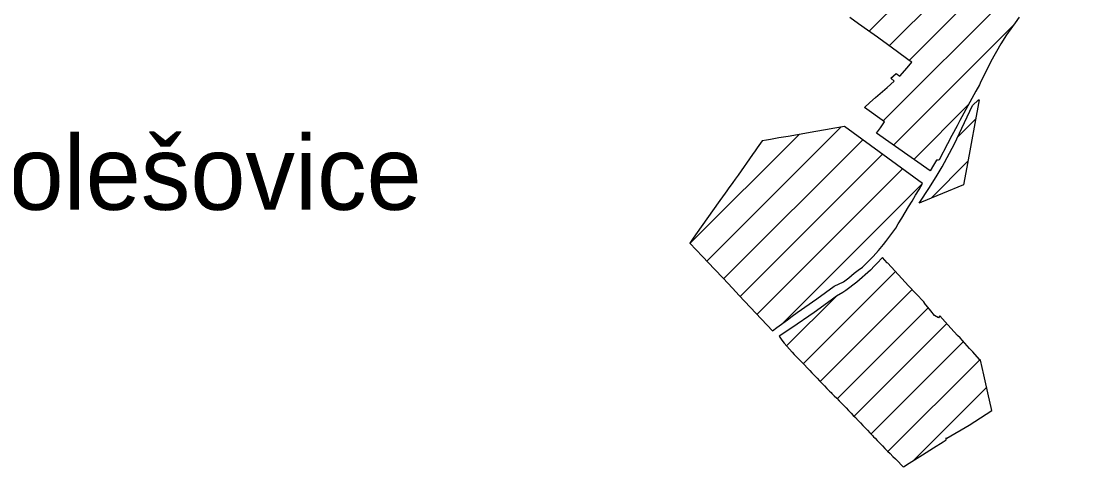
# Model space of a CAD drawing. Extents: x -552716 to -540720, y -1192685 to -1177912.
# Drawn here: x -547709 to -545764, y -1186023 to -1185200 of the extents above; entities that cross this region are included whole.
import ezdxf

# ---------------------------------------------------------------- set-up
doc = ezdxf.new("R2010")
doc.units = 0
for name, color, linetype in [('Default', 7, 'Continuous'), ('Vrstva 1', 7, 'Continuous'), ('Vrstva 2', 7, 'Continuous')]:
    doc.layers.add(name, color=color, linetype=linetype)

msp = doc.modelspace()

# ---------------------------------------------------------------- linework, layer by layer
at = {"layer": 'Default'}
for points in [[(-546032.8, -1185476.8), (-546131.5, -1185407.2), (-546124.2, -1185397.1), (-546116.6, -1185386.4), (-546153.9, -1185359.5), (-546143.8, -1185350.6), (-546133.2, -1185341.3), (-546112.1, -1185322.6), (-546098.8, -1185310.9), (-546105.4, -1185305.9), (-546095.4, -1185296.8), (-546088.6, -1185301.8), (-546075.2, -1185286.3), (-546066.4, -1185276.4), (-546072.9, -1185271.6), (-546073.8, -1185271), (-546093, -1185256.9), (-546111.2, -1185243.6), (-546127, -1185232.1), (-546129.5, -1185230.3), (-546148.3, -1185216.9), (-546164.6, -1185205.2), (-546181, -1185193.5)], [(-545868.2, -1185193.3), (-545875.9, -1185203.4), (-545891.6, -1185225.4), (-545902, -1185242.2), (-545921, -1185275.1), (-545933.9, -1185301.3), (-545939, -1185311.9), (-545941.9, -1185317.7), (-545948.1, -1185329.7), (-545977.7, -1185383.6), (-545981.8, -1185391), (-545983.1, -1185393.3), (-545992.6, -1185411.5), (-546000.8, -1185427.1), (-546016.1, -1185456.1), (-546018.1, -1185456.7), (-546019.9, -1185456.8), (-546020.9, -1185456.8), (-546026.4, -1185466.2), (-546032.8, -1185476.8)], [(-546190.8, -1185394.7), (-546208.3, -1185397.7), (-546225.8, -1185400.8), (-546243.2, -1185403.9), (-546260.4, -1185406.9), (-546277.6, -1185409.9), (-546294.7, -1185413), (-546311.9, -1185416), (-546327.1, -1185418.7), (-546334.7, -1185420), (-546342.3, -1185421.4), (-546351.5, -1185434.3), (-546355.5, -1185439.9), (-546360.3, -1185446.7), (-546387, -1185484.4), (-546392.4, -1185491.9), (-546396.8, -1185498.2), (-546401.4, -1185504.6), (-546403.9, -1185508.2), (-546407.5, -1185513.3), (-546410.7, -1185517.7), (-546420.4, -1185531.5), (-546465.2, -1185594.6), (-546470.7, -1185602.4), (-546476.1, -1185609.9), (-546452.7, -1185634.5), (-546430.6, -1185657.9), (-546414.7, -1185674.7), (-546397.5, -1185693), (-546384.8, -1185706.7), (-546323.2, -1185771.6), (-546315.4, -1185765.8), (-546295.7, -1185751.2), (-546287.2, -1185744.9), (-546278.1, -1185738.1), (-546241.9, -1185712.8), (-546209.4, -1185689.4), (-546192.4, -1185681.7), (-546182.9, -1185673.9), (-546172.8, -1185665.7), (-546165.2, -1185660), (-546157.4, -1185654.2), (-546147.1, -1185644.1), (-546137.9, -1185634.5), (-546127.7, -1185623.7), (-546118.4, -1185612.3), (-546114.3, -1185606.8), (-546110.8, -1185602.1), (-546096.1, -1185582.5), (-546091.4, -1185574.7), (-546085.1, -1185564.2), (-546078.8, -1185553.6), (-546072.4, -1185543), (-546066.1, -1185532.4), (-546059.6, -1185521.6), (-546053.1, -1185510.8), (-546046.6, -1185499.9), (-546190.8, -1185394.7)], [(-546311.4, -1185781.9), (-546306, -1185789.2), (-546302, -1185794.3), (-546297.2, -1185800.1), (-546292.3, -1185805.7), (-546287.4, -1185811), (-546283.2, -1185815.4), (-546278.7, -1185820.1), (-546273.6, -1185825.4), (-546269.3, -1185829.9), (-546264.6, -1185834.8), (-546259.5, -1185840.1), (-546254.8, -1185844.9), (-546250.6, -1185849.3), (-546245.7, -1185854.4), (-546241.1, -1185859.1), (-546236.5, -1185863.9), (-546232.3, -1185868.3), (-546227.5, -1185873.2), (-546222.9, -1185878.1), (-546218.2, -1185882.9), (-546215.5, -1185885.7), (-546214.1, -1185887.2), (-546209.4, -1185891.8), (-546205, -1185896.3), (-546200.6, -1185900.7), (-546196.1, -1185905.2), (-546191.6, -1185909.7), (-546187.7, -1185913.8), (-546183, -1185918.7), (-546178.5, -1185923.4), (-546174.4, -1185927.7), (-546170.5, -1185931.8), (-546165.3, -1185937.2), (-546161, -1185941.8), (-546156.5, -1185946.5), (-546151.4, -1185951.9), (-546148.1, -1185955.3), (-546143.7, -1185960), (-546139.2, -1185964.7), (-546136.9, -1185967.2), (-546134.3, -1185969.9), (-546130.3, -1185974.1), (-546125.4, -1185979.2), (-546120.6, -1185984.1), (-546116.1, -1185988.9), (-546111, -1185994), (-546106.5, -1185998.4), (-546101.3, -1186003.7), (-546096.7, -1186008.2), (-546091.3, -1186013.7), (-546086.2, -1186018.8), (-546083.2, -1186021.8), (-546082.2, -1186022.9), (-546080.6, -1186021.8), (-546076.5, -1186019.2), (-546047, -1186000.5), (-546026.6, -1185987.7), (-546008.9, -1185976.4), (-546003, -1185972.6), (-546002.8, -1185969.5), (-546001.7, -1185969.6), (-545960.7, -1185945.6), (-545918.7, -1185918.8), (-545926, -1185885.9), (-545933.7, -1185852.9), (-545939.8, -1185826.2), (-545941.4, -1185824.5), (-545954.2, -1185810.5), (-545959.8, -1185804.3), (-545977.5, -1185784.9), (-545981.9, -1185780.2), (-545994.2, -1185766.6), (-546010, -1185749.4), (-546014.8, -1185744.2), (-546017.4, -1185747.8), (-546024.7, -1185743.3), (-546031.5, -1185735), (-546043.2, -1185720.5), (-546043, -1185720.1), (-546044.3, -1185718.6), (-546058.4, -1185703.3), (-546072.3, -1185688.9), (-546085, -1185675.1), (-546097.7, -1185661.2), (-546110.9, -1185647.1), (-546111.7, -1185646.2), (-546120.7, -1185636.6), (-546130.9, -1185647.6), (-546135.1, -1185652), (-546142.9, -1185659.6), (-546167.8, -1185681.8), (-546188.3, -1185697.2), (-546193.9, -1185700.9), (-546205.6, -1185708.1), (-546215.5, -1185715.4), (-546246.6, -1185737.9), (-546287.6, -1185766.5), (-546311.4, -1185781.9)]]:
    msp.add_lwpolyline(points, dxfattribs=at)
msp.add_lwpolyline([(-545971, -1185502.5), (-546048.8, -1185534.4), (-546052.7, -1185536), (-546034.1, -1185507.4), (-546019.5, -1185484.8), (-546010.2, -1185469.5), (-545987.9, -1185426.8), (-545983.6, -1185417.7), (-545969.1, -1185387.4), (-545954.3, -1185356.2), (-545943.6, -1185345.5), (-545942.4, -1185345.6), (-545964.8, -1185469.6)], close=True, dxfattribs=at)
at = {"layer": 'Vrstva 2'}
for p, q in [((-546145, -1185219.2), (-545826.9, -1184901.1)), ((-546108, -1185245.9), (-545806.3, -1184944.2)), ((-546071.3, -1185272.8), (-545797.4, -1184998.9)), ((-546119.3, -1185384.5), (-545763.8, -1185029)), ((-546100.4, -1185429.2), (-545879.2, -1185208)), ((-546104.8, -1185306.3), (-546095.3, -1185296.8)), ((-546063, -1185455.5), (-545961.3, -1185353.8)), ((-546444.6, -1185643.1), (-546197.3, -1185395.8)), ((-545982, -1185414.5), (-545948.8, -1185381.3)), ((-546475.6, -1185610.5), (-546274.5, -1185409.4)), ((-546413.6, -1185675.8), (-546157.1, -1185419.3)), ((-546382.9, -1185708.7), (-546120.3, -1185446.1)), ((-546351.9, -1185741.3), (-546083.5, -1185473)), ((-546031, -1185527.1), (-545962.9, -1185459)), ((-546305.1, -1185758.2), (-546046.7, -1185499.8)), ((-546266.7, -1185832.5), (-546096.6, -1185662.4)), ((-546297.5, -1185799.7), (-546206.9, -1185709)), ((-546235.5, -1185865), (-546066, -1185695.4)), ((-546204.1, -1185897.2), (-546036.1, -1185729.2)), ((-546172.7, -1185929.5), (-546001.7, -1185758.4)), ((-546141.7, -1185962.1), (-545971.3, -1185791.7)), ((-546110.5, -1185994.5), (-545941, -1185825)), ((-546063, -1186010.7), (-545928.3, -1185876))]:
    msp.add_line(p, q, dxfattribs=at)

# ---------------------------------------------------------------- texts
at = {"layer": 'Vrstva 1'}
msp.add_text('Polešovice', height=136.69, dxfattribs=at).set_placement((-547854.4, -1185548.5))

doc.saveas('drawing.dxf')
